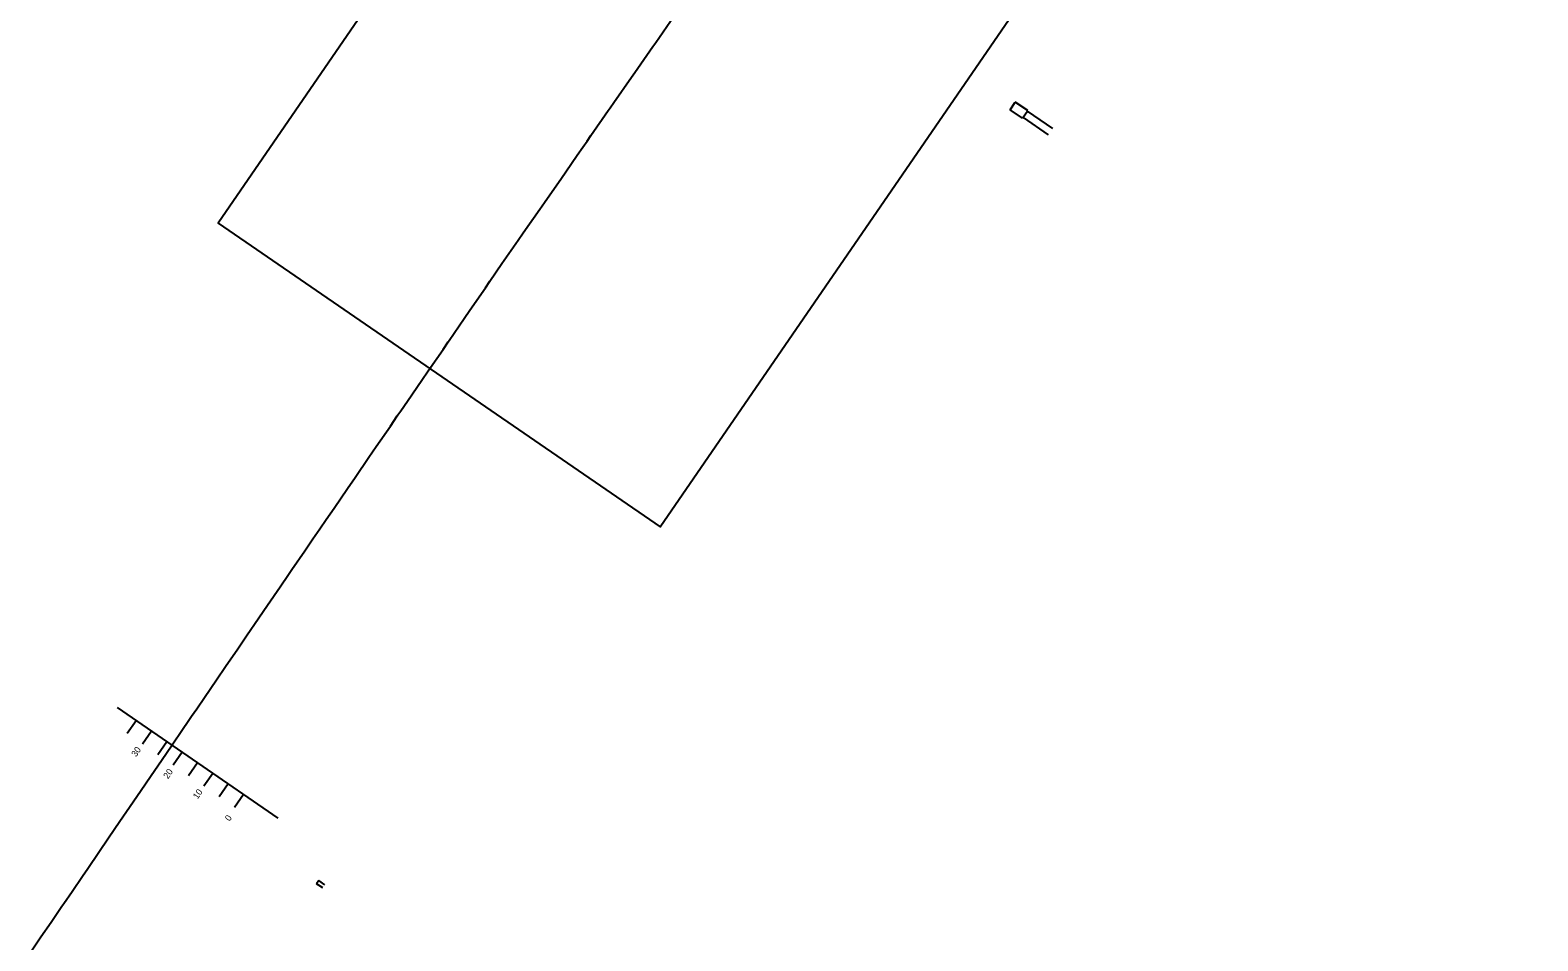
# Model space of a CAD drawing. Extents: x 2379438 to 2380801, y 331550 to 333566.
# Drawn here: x 2379808.2 to 2380212.9, y 332156.6 to 332401.2 of the extents above; entities that cross this region are included whole.
import ezdxf

# ---------------------------------------------------------------- set-up
doc = ezdxf.new("R2010")
doc.units = 0
for name, color, linetype in [('Auto Dimensioning', 7, 'Continuous'), ('E_SMU_Mis_Existing_Ground_Lines', 7, 'Continuous'), ('E_SMU_Piles_concrete', 7, 'Continuous'), ('P_SMU_Steel_Pile', 7, 'Continuous'), ('Rip Rap', 7, 'Continuous')]:
    doc.layers.add(name, color=color, linetype=linetype)

msp = doc.modelspace()

# ---------------------------------------------------------------- linework, layer by layer
at = {"layer": 'Auto Dimensioning'}
for p, q in [((2379831.49, 332219.26), (2379874.67, 332189.59)), ((2379836.59, 332215.75), (2379834.21, 332212.28)), ((2379840.72, 332212.92), (2379838.33, 332209.45)), ((2379844.84, 332210.09), (2379842.45, 332206.62)), ((2379848.96, 332207.26), (2379846.57, 332203.79)), ((2379853.08, 332204.43), (2379850.69, 332200.96)), ((2379857.2, 332201.6), (2379854.81, 332198.12)), ((2379861.32, 332198.77), (2379858.93, 332195.29)), ((2379865.44, 332195.94), (2379863.06, 332192.46))]:
    msp.add_line(p, q, dxfattribs=at)
for points in [[(2379977.32, 332267.82), (2380212.89, 332610.7), (2380094.2, 332692.24), (2379858.63, 332349.37)], [(2379858.63, 332349.37), (2379977.32, 332267.82), (2380212.89, 332610.7), (2380094.2, 332692.24)]]:
    msp.add_lwpolyline(points, close=True, dxfattribs=at)
at = {"layer": 'E_SMU_Mis_Existing_Ground_Lines'}
msp.add_lwpolyline([(2379808.17, 332153.45), (2379811.06, 332157.67), (2379813.79, 332161.68), (2379816.7, 332165.94), (2379817.18, 332166.64), (2379819.41, 332169.9), (2379822.19, 332173.98), (2379823.62, 332176.07), (2379826.6, 332180.45), (2379829.24, 332184.31), (2379832.27, 332188.75), (2379834.87, 332192.55), (2379837.94, 332197.05), (2379840.49, 332200.78), (2379843.61, 332205.35), (2379846.11, 332209.02), (2379849.27, 332213.65), (2379850.44, 332215.36), (2379851.52, 332216.96), (2379852.87, 332218.95), (2379854.96, 332222.01), (2379858.22, 332226.75), (2379860.6, 332230.26), (2379863.9, 332235.06), (2379866.23, 332238.51), (2379869.58, 332243.38), (2379871.87, 332246.75), (2379875.26, 332251.69), (2379877.5, 332255), (2379878.27, 332256.11), (2379878.42, 332256.34), (2379881.9, 332261.39), (2379884.08, 332264.59), (2379885.91, 332267.24), (2379887.63, 332269.74), (2379889.74, 332272.84), (2379893.38, 332278.12), (2379895.4, 332281.08), (2379899.13, 332286.5), (2379901.06, 332289.33), (2379904.88, 332294.87), (2379906.72, 332297.58), (2379906.91, 332297.84), (2379907.66, 332298.94), (2379909.45, 332301.54), (2379913.33, 332307.2), (2379915.04, 332309.69), (2379919, 332315.45), (2379920.38, 332317.46), (2379920.64, 332317.83), (2379924.68, 332323.71), (2379926.22, 332325.95), (2379930.36, 332331.97), (2379931.6, 332333.78), (2379934.83, 332338.48), (2379939.2, 332344.74), (2379940.53, 332346.7), (2379944.98, 332353.07), (2379946.24, 332354.92), (2379950.76, 332361.4), (2379951.95, 332363.14), (2379955.03, 332367.56), (2379956.55, 332369.73), (2379957.66, 332371.35), (2379958.71, 332372.9), (2379963.36, 332379.55), (2379963.88, 332380.29), (2379964.86, 332381.71), (2379969.61, 332388.52), (2379970.49, 332389.8), (2379975.35, 332396.75), (2379976.13, 332397.88), (2379981.09, 332404.98)], dxfattribs=at)
at = {"layer": 'E_SMU_Piles_concrete'}
for p, q in [((2380075.82, 332379.37), (2380082.57, 332374.73)), ((2380074.69, 332377.72), (2380081.43, 332373.08))]:
    msp.add_line(p, q, dxfattribs=at)
at = {"layer": 'P_SMU_Steel_Pile'}
for p, q in [((2379885.64, 332172.79), (2379885.08, 332171.97)), ((2379887.29, 332171.66), (2379885.64, 332172.79)), ((2379886.72, 332170.84), (2379885.08, 332171.97))]:
    msp.add_line(p, q, dxfattribs=at)
at = {"layer": 'Rip Rap'}
for p, q in [((2380071.21, 332379.81), (2380072.62, 332381.87)), ((2380074.55, 332377.51), (2380071.21, 332379.81)), ((2380075.96, 332379.57), (2380072.62, 332381.87)), ((2380074.55, 332377.51), (2380075.96, 332379.57))]:
    msp.add_line(p, q, dxfattribs=at)

# ---------------------------------------------------------------- texts
at = {"layer": 'Auto Dimensioning'}
for s, height, p in [('30', 1.717, (2379836.6, 332205.88)), ('20', 1.717, (2379845.18, 332199.98)), ('10', 1.717, (2379853.11, 332194.54)), ('0', 1.72, (2379861.72, 332188.62))]:
    msp.add_text(s, height=height, rotation=55.5093, dxfattribs=at).set_placement(p)

doc.saveas('drawing.dxf')
